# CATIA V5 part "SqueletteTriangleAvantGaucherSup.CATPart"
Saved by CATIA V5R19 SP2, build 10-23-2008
Part number: SqueletteTriangleAvantGaucherSup
Bounding box of the stored display mesh (mm): x 625.259 to 627.535, y -141.143 to -59.1, z -193.65 to -191.381
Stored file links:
  D:\Mes Documents\ressource\CATIA\Ensemble Catia\Voiture_Telecommmande\SchemaCinematiqueFinal\SqueletteTriangleAvantGaucherSup.CATPart
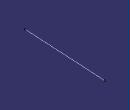
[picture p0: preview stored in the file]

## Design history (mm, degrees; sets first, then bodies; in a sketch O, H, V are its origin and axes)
AxisSystem1: origin (0, 0, 0), X (1, 0, 0), Y (0, 1, 0), Z (0, 0, 1)
Set1
  Point1 to Point4: stored without definition
  Line1: stored without definition
Body1 (main body)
